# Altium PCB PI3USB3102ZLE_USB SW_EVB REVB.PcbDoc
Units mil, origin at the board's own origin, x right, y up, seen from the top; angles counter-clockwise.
Board outline 3200 x 2700 mil, 4 copper layers (Top Layer, InternalPlane1, InternalPlane2, Bottom Layer); 46 components, 36 nets, 154 pads, 58 vias.
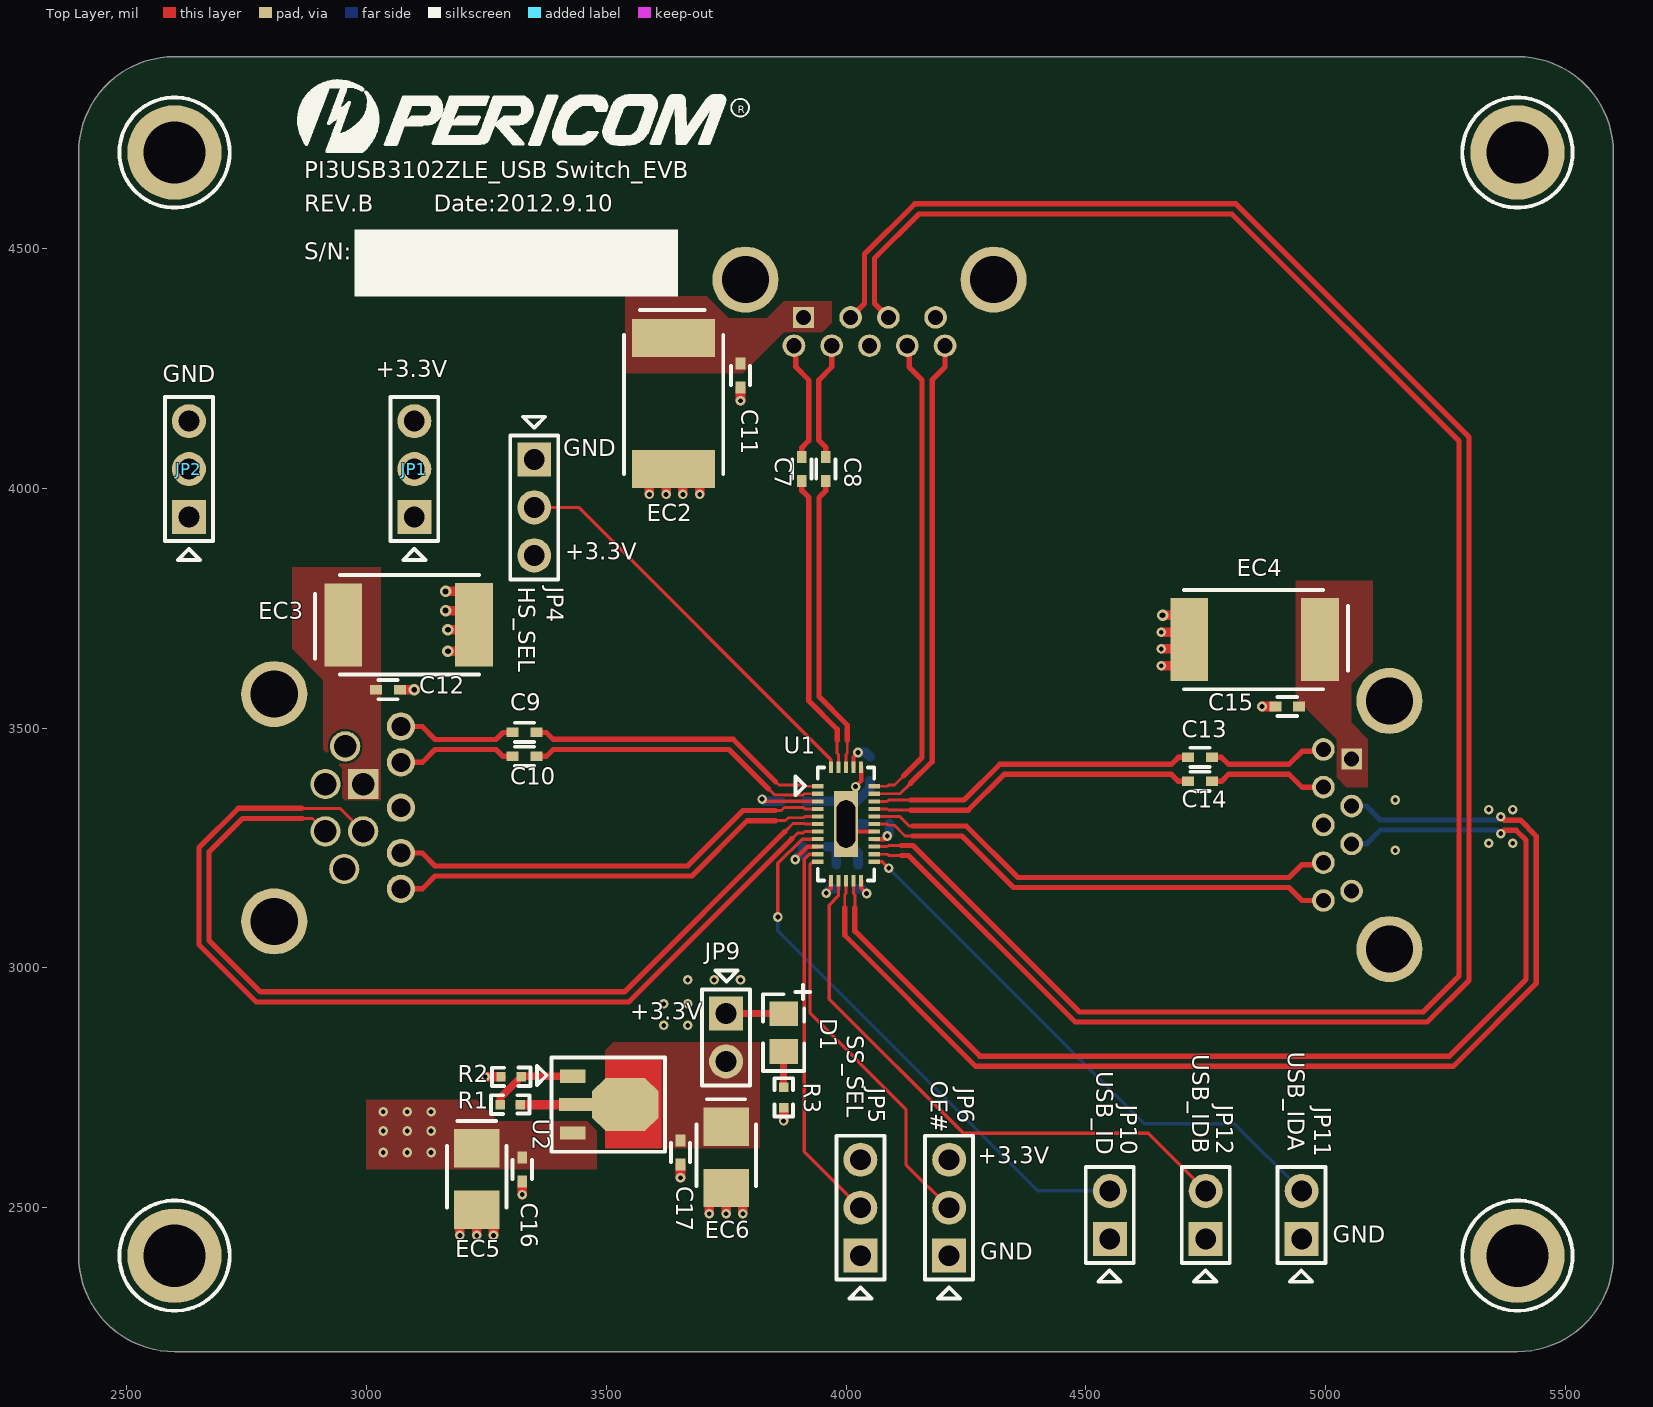
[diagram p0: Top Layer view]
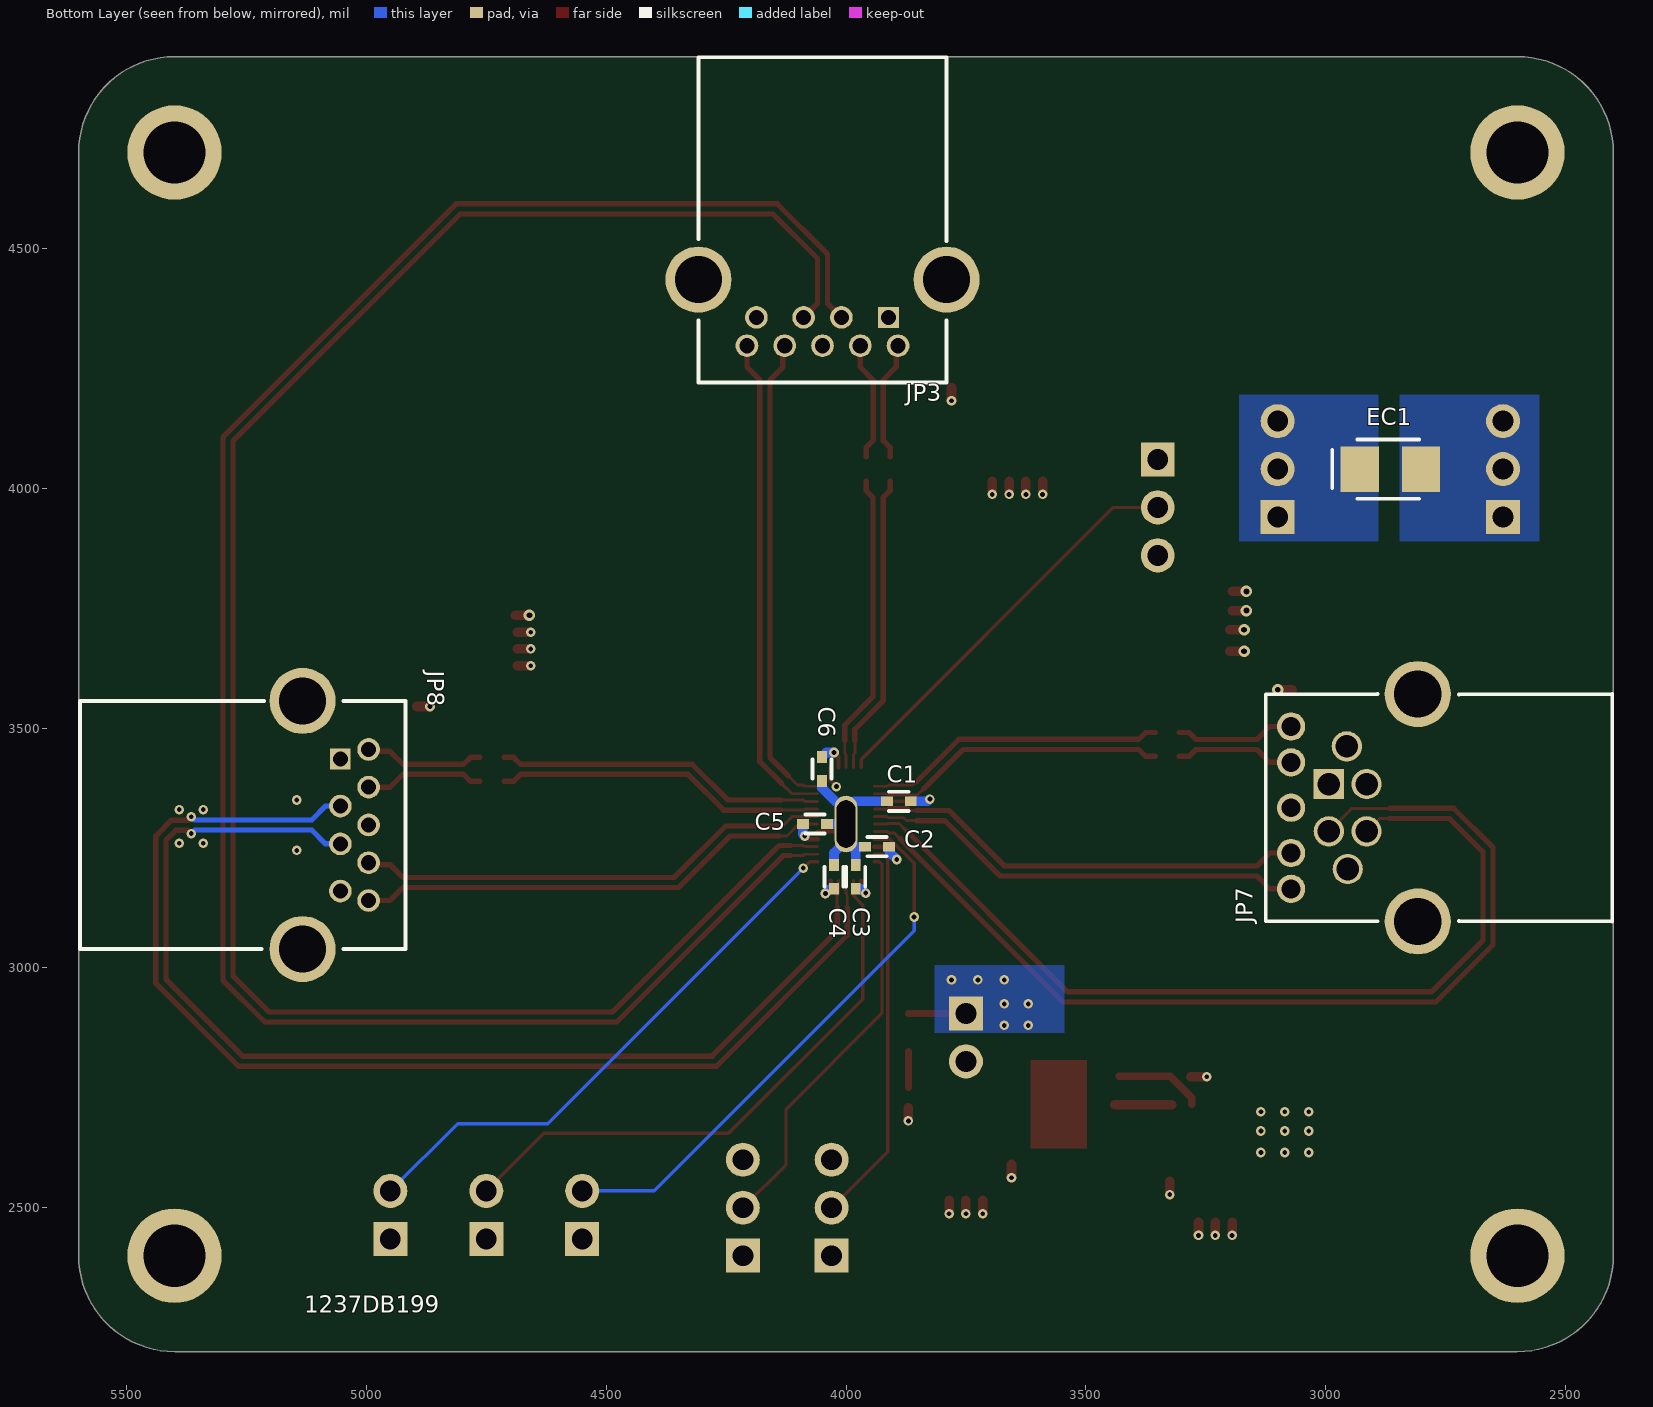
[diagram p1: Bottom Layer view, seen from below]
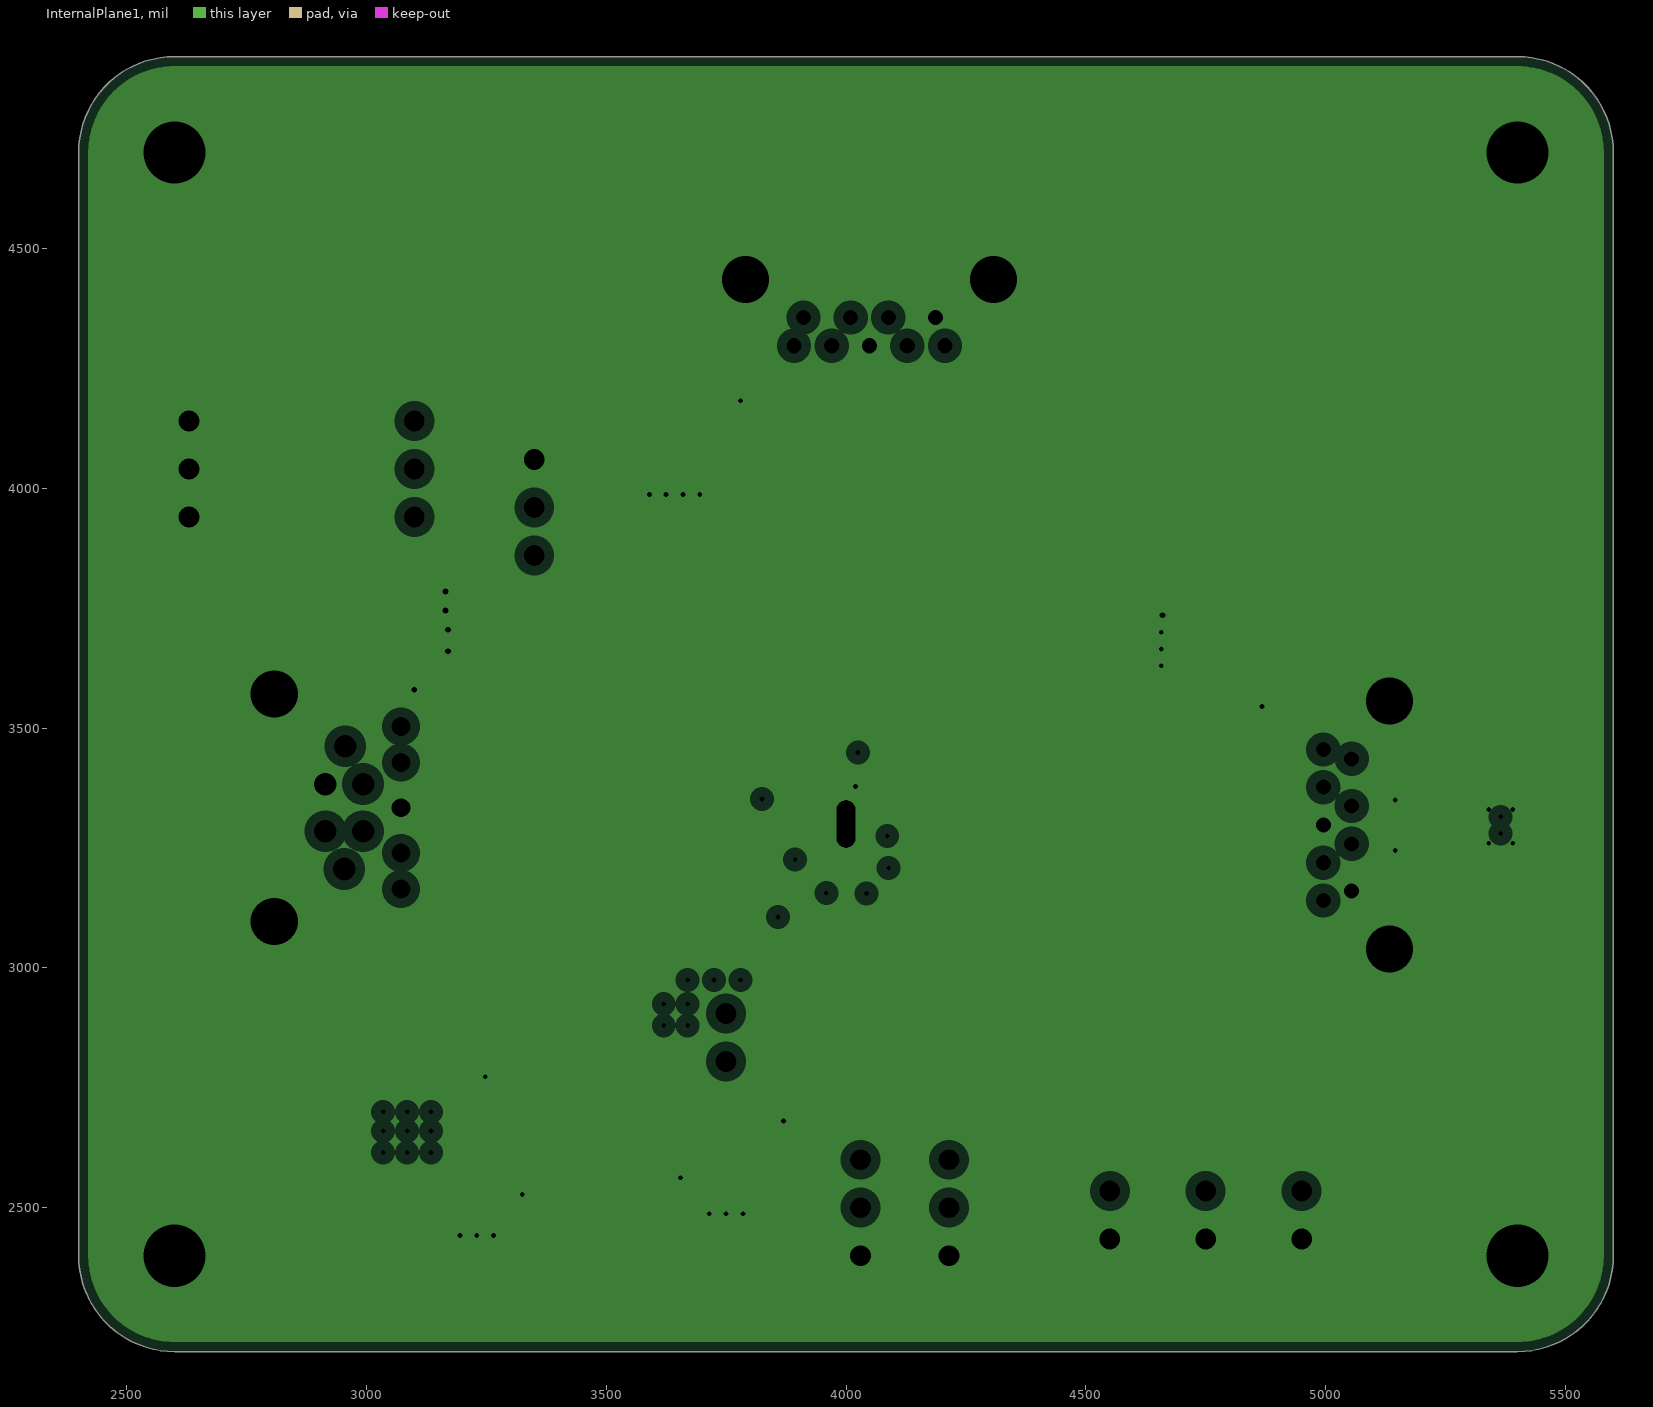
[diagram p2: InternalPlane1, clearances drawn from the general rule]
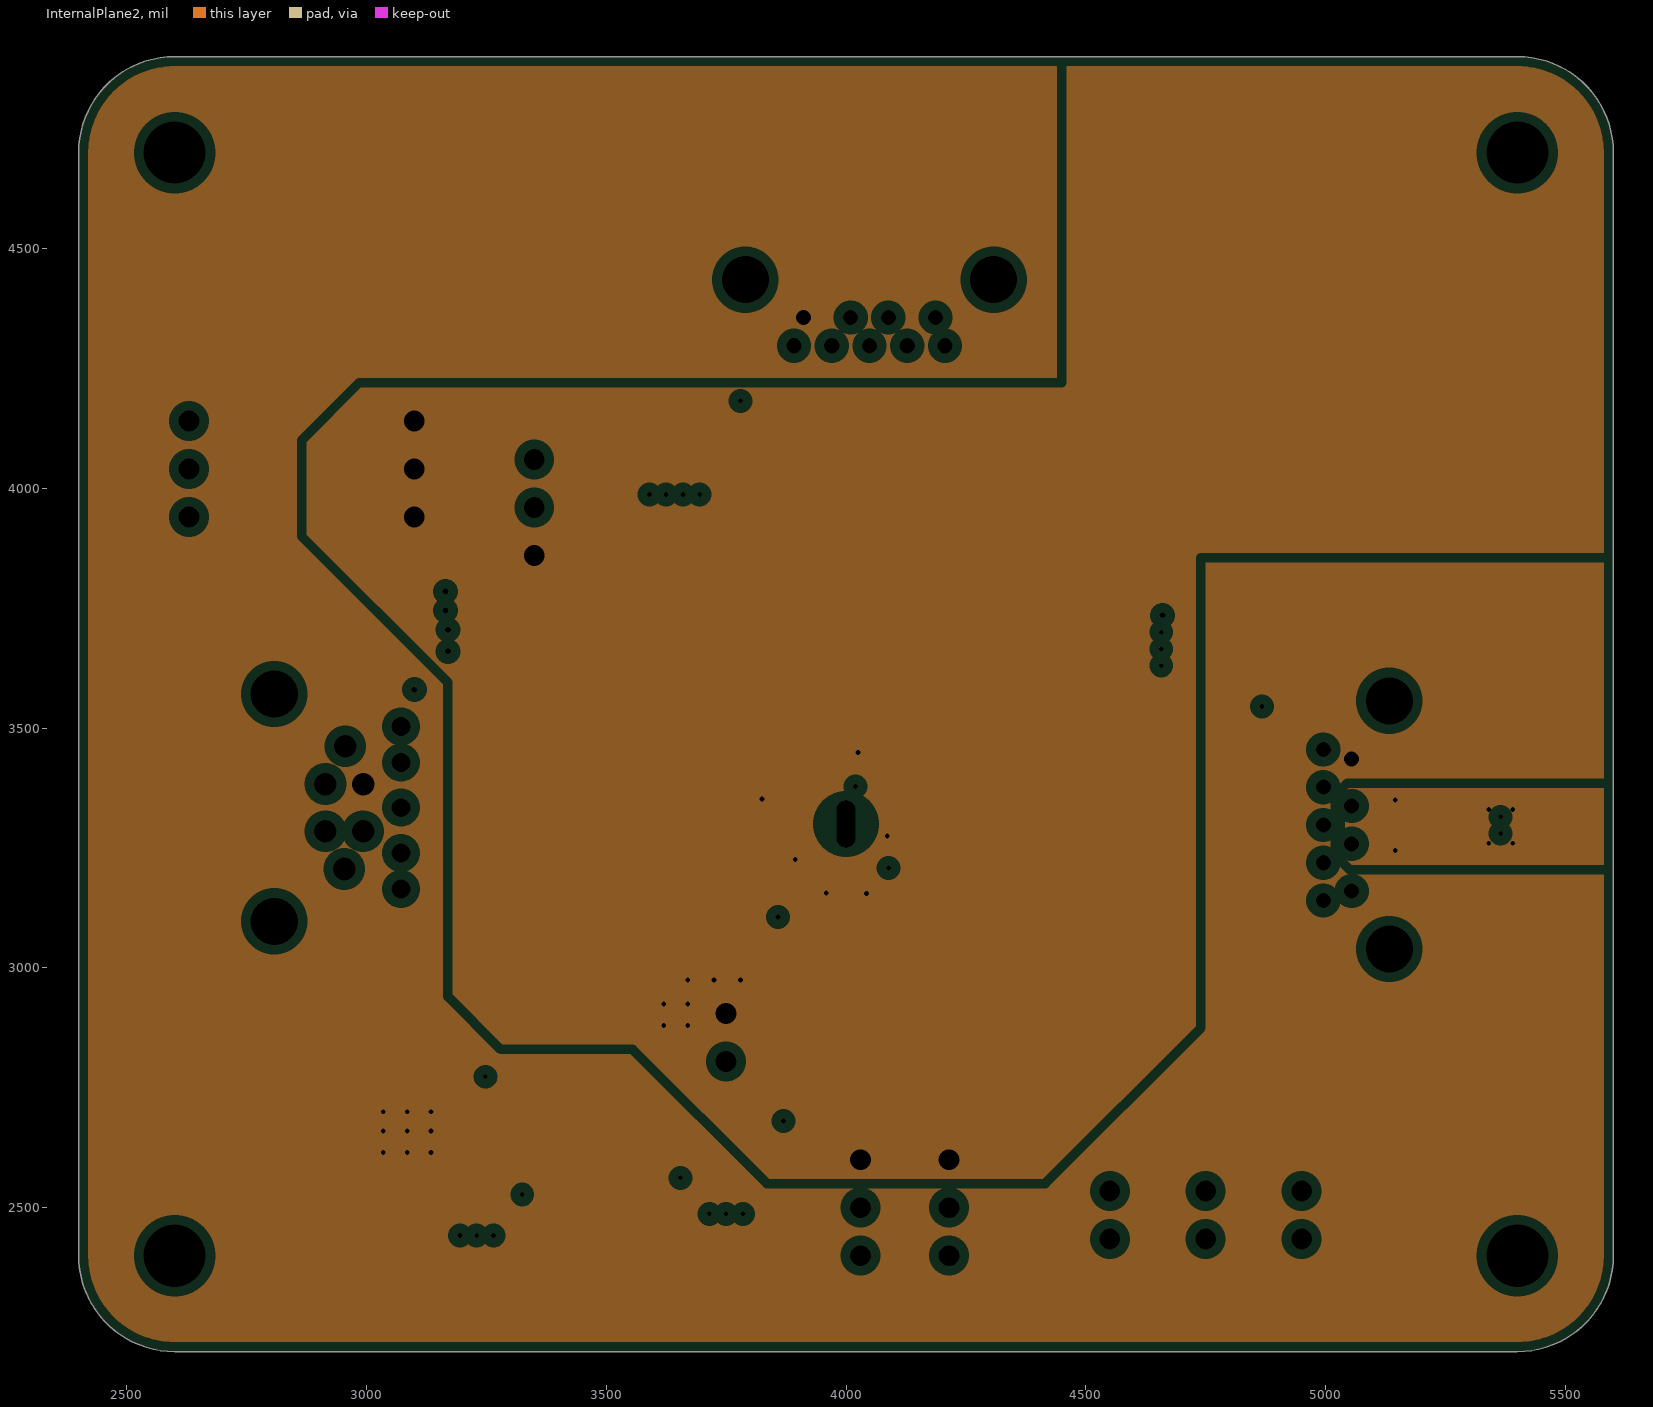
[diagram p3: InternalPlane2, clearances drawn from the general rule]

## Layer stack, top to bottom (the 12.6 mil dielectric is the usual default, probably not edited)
Top Layer: signal copper 1.4
Dielectric: core 12.6, FR-4, Dk 4.8
InternalPlane1: plane copper 1.4, net GND
Dielectric: prepreg 12.6, FR-4, Dk 4.8
InternalPlane2: plane copper 1.4, net VBUS_5V
Dielectric: core 12.6, FR-4, Dk 4.8
Bottom Layer: signal copper 1.4

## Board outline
2400,2400 ccw(c2600,2400) 2600,2200 5400,2200 ccw(c5400,2400) 5600,2400 5600,4700 ccw(c5400,4700) 5400,4900 2600,4900 ccw(c2600,4700) 2400,4700

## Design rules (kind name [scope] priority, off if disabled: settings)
Clearance [All] p1: gap=5
ComponentClearance [All] p1: gap=0 collisioncheckmode=3 verticalgap=0
DiffPairsRouting [All] p1: maxlimit=10 minlimit=10 mostfreqgap=10 maxuncoupledlength=500
HoleSize [All] p1: absolutevalues=TRUE maxlimit=500 minlimit=1 maxpercent=80.000 minpercent=20.000
PlaneClearance [All] p1: clearance=20
PlaneConnect [All] p1: planeconnectstyle=Direct reliefexpansion=20 reliefentries=4 reliefconductorwidth=10 reliefairgap=10
PolygonConnect [All] p1: connectstyle=Direct reliefconductorwidth=10 reliefentries=4 polygonreliefangle="90 Angle"
RoomDefinition "PI3USB3102ZLE USB SW EV" [InComponentClass('PI3USB3102ZLE USB SW EV')] p1: confinementstyle=ConfineIn formatcopy=TRUE lockcomponents=FALSE outline 80,235 17230,235 17230,6635 80,6635
RoutingVias [All] p1: holewidth=28 width=50 viastyle="Through Hole" minholewidth=8 minwidth=10 maxholewidth=28 maxwidth=50
SolderMaskExpansion [All] p1: expansion=4
TestPointUsage [All] p1: valid=0 allowmultiple=FALSE
Testpoint [All] p1: side=15 testpointundercomponent=TRUE minsize=40 maxsize=100 preferedsize=60 minholesize=0 maxholesize=40 preferedholesize=32 testpointgrid=1 style=1023 order=0-112345678
Width [All] p1: maxlimit=150 minlimit=5 preferedwidth=10
14 further rules are at their usual default settings.

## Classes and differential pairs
component class "PI3USB3102ZLE USB SW EV": C1 C2 C3 C4 C5 C6 C7 C8 C9 C10 C11 C12 C13 C14 C15 C16 C17 D1 EC1 EC2 EC3 EC4 EC5 EC6 JP1 JP2 JP3 JP4 JP5 JP6 JP7 JP8 JP9 JP10 JP11 JP12 R1 R2 R3 U1 U2
differential pair NewDifferentialPair12: +TX+B -TX-B
differential pair NewDifferentialPair11: +TX+A -TX-A
differential pair NewDifferentialPair10: +TX- -TX+
differential pair NewDifferentialPair9: +RX+B -RX-B
differential pair NewDifferentialPair8: +RX+A -RX-A
differential pair NewDifferentialPair7: +RX- -RX+
differential pair NewDifferentialPair6: +NetC13_2 -NetC14_2
differential pair NewDifferentialPair5: +NetC7_2 -NetC8_2
differential pair NewDifferentialPair4: +NetC10_1 -NetC9_1
differential pair NewDifferentialPair3: +D-B -D+B
differential pair NewDifferentialPair2: +D-A -D+A
differential pair NewDifferentialPair1: +D+ -D-

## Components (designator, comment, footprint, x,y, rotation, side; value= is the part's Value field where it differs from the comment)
C1 "0.1uF" CAP@CC_0402 3890,3347.24 r0 bottom
C2 "0.1uF" CAP@CC_0402 3935,3252.76 r0 bottom
C3 "0.1uF" CAP@CC_0402 3980,3190 r90 bottom
C4 "0.1uF" CAP@CC_0402 4025,3190 r90 bottom
C5 "0.1uF" CAP@CC_0402 4065,3300 r180 bottom
C6 "0.1uF" CAP@CC_0402 4050,3415 r270 bottom
C7 "0.1u" CC_0402 3908,4040 r90 top
C8 "0.1u" CC_0402 3958,4040 r90 top
C9 "0.1u" CC_0402 3330,3491 r0 top
C10 "0.1u" CC_0402 3330,3441 r0 top
C11 "0.1uF" CC_0402 3780,4235 r270 top
C12 "0.1uF" CAP@CC_0402 3045,3580 r0 top
C13 "0.1u" CC_0402 4738,3439 r0 top
C14 "0.1u" CC_0402 4738,3389 r0 top
C15 "0.1uF" CAP@CC_0402 4920,3545 r180 top
C16 "0.1uF" CC_0402 3325,2580 r270 top
C17 "0.1uF" CC_0402 3655,2615 r270 top
D1 "LED_G" LED_0805 3870,2865 r270 top
EC1 "22UF" CAP@CT_3528 2865,4040 r180 bottom
EC2 "100U" CT_7343 3640,4195 r90 top
EC3 "100UF" CAP@CT_7343 3070,3715 r180 top
EC4 "100UF" CAP@CT_7343 4870,3685 r0 top
EC5 "22uF" CT_3528 3230,2560 r270 top
EC6 "22uF" CT_3528 3750,2605 r270 top
JP1 "3x1 Pin Header" "3x1 Pin Header" 3100,3940 r90 top
JP2 "3x1 Pin Header" "3x1 Pin Header" 2630,3940 r90 top
JP3 "CON_USB3.0 TA_RECEPTACLE" "CON_USB3.0 TA_RECEPTACLE" 4049,4435 r0 bottom
JP4 "3x1 Pin Header" "3x1 Pin Header" 3350,4060 r270 top
JP5 "3x1 Pin Header" "3x1 Pin Header" 4030,2400 r90 top
JP6 "3x1 Pin Header" "3x1 Pin Header" 4215,2400 r90 top
JP7 "CON_USB3.0 TB_RECEPTACLE" "CON_USB3.0 TB_RECEPTACLE" 3072,3334 r90 bottom locked
JP8 "CON_USB3.0 TA_RECEPTACLE" "CON_USB3.0 TA_RECEPTACLE" 5133,3298 r270 bottom locked
JP9 "2x1 Pin Header" "2x1 Pin Header" 3750,2905 r270 top
JP10 "2x1 Pin Header" "2x1 Pin Header" 4550,2435 r90 top
JP11 "2x1 Pin Header" "2x1 Pin Header" 4950,2435 r90 top
JP12 "2x1 Pin Header" "2x1 Pin Header" 4750,2435 r90 top
R1 "NP" R_0402 3300,2715 r0 top
R2 "0" R_0402 3302,2773 r180 top
R3 "510" R_0402 3870,2730 r270 top
U1 "PI3USB3102ZLE@TQFN32" TQFN32_3X6 4000,3300 r0 top locked
U2 "CJ1117-ADJ" Pow_SOT_89 3485,2715 r270 top
? "Comment" HOLE5M3M3 5400,2400 r0 top
? "Comment" HOLE5M3M3 2600,2400 r0 top
? "Comment" HOLE5M3M3 2600,4700 r0 top
? "Comment" HOLE5M3M3 5400,4700 r0 top
? "Comment" PSC_LOG 2965,4805 r0 top

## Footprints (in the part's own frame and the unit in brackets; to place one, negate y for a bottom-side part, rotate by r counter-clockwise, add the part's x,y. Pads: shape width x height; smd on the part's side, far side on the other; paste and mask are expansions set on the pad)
"2x1 Pin Header" [mm] "Pin Header 2x1 Pitch 2.54mm"
  rect 1.8x1.8 hole 1.1: 1(0,0)
  round 1.8 hole 1.1: 2(2.54,0)
  silkscreen extent -2.27,-1.27 3.81,1.27
"3x1 Pin Header" [mm] "Pin Header 3x1 Pitch 2.54mm"
  rect 1.8x1.8 / inner round 1.8 / far side rect 1.8x1.8 hole 1.1: 1(0,0)
  round 1.8 hole 1.1: 2(2.54,0) 3(5.08,0)
  silkscreen extent -2.27,-1.27 6.35,1.27
CAP@CC_0402 [mil]
  rect 25x20 smd: 1(-25,0) 2(25,0)
  silkscreen extent -20,-20 20,20
CAP@CT_3528 [mil]
  rect 80x95 smd: 1(-64,0) 2(64,0)
  silkscreen extent -121,-62 60,62
CAP@CT_7343 [mm]
  rect 2x4.4 smd: 1(3,0) 2(-3.926,-0.011)
  silkscreen extent -4.19,-2.64 4.5,2.62
CC_0402 [mil]
  rect 25x20 smd: 1(-25,0) 2(25,0)
  silkscreen extent -20,-20 20,20
"CON_USB3.0 TA_RECEPTACLE" [mm]
  rect 1.1x1.1 hole 0.8: 1(-3.5,2)
  round 1.2 hole 0.8: 2(-1,2) 3(1,2) 4(3.5,2) 5(4,3.5) 6(2,3.5) 7(0,3.5) 8(-2,3.5) 9(-4,3.5)
  round 3.5 hole 2.5: 20(-6.57,0) 20(6.57,0)
  silkscreen extent -6.57,-11.78 6.57,5.45
"CON_USB3.0 TB_RECEPTACLE" [mm]
  rect 1.6x1.6 hole 1.2: 1(1.25,-2)
  round 1.6 hole 1.2: 2(-1.25,-2) 3(-1.25,-4) 4(1.25,-4) 10(3.25,-2.95) 11(-3.25,-3)
  round 1.5 hole 1: 5(-4.3,0) 6(-2.4,0) 7(0,0) 8(2.4,0) 9(4.3,0)
  round 3.5 hole 2.5: 20(-6.02,-6.71) 20(6.02,-6.71)
  silkscreen extent -6.02,-17.01 6.02,1.34
CT_3528 [mil]
  rect 80x95 smd: 1(-64,0) 2(64,0)
  silkscreen extent -121,-62 60,62
CT_7343 [mm]
  rect 2x4.4 smd: 1(3,0) 2(-3.926,-0.011)
  silkscreen extent -4.19,-2.64 4.5,2.62
HOLE5M3M3 [mm] "HOLE, Plated"
  round 5 hole 3.3: 0(0,0)
  silkscreen extent -2.92,-2.92 2.92,2.92
LED_0805 [mm] "Chip Resistor; Body 2 x 1.3 mm (LxW typ)"
  rect 1.3x1.5 smd: 1(-1,0) 2(1,0)
  silkscreen extent -2.54,-1.09 2.03,1.4
Pow_SOT_89 [mm] "SOT-89; Body 4.6 x 4.25 mm, inc. leads (LxW max)"
  rect 0.7x1.35 smd: 1(-1.5,-1.388) 3(1.5,-1.388)
  oct 2.8x3.5 smd: 2(0,1.388)
  rect 0.7x1.9 smd: 2(0,-1.163)
  Top Layer region: -2.346,0.336 -2.346,3.302 2.322,3.302 2.323,3.303 2.323,0.338 2.325,0.336
  silkscreen extent -2.5,-3.28 2.5,3.49
PSC_LOG [mil]
  silkscreen extent -107,-103 833,45
R_0402 [mm]
  rect 0.5x0.5 smd: 1(-0.532,-0.001) 2(0.54,-0.001)
  silkscreen extent -1.02,-0.49 1.02,0.49
TQFN32_3X6 [mm]
  rect 0.6x0.22 smd: 1(-1.5,2) 2(-1.5,1.6) 3(-1.5,1.2) 4(-1.5,0.8) 5(-1.5,0.4) 6(-1.5,0) 7(-1.5,-0.4) 8(-1.5,-0.8) 9(-1.5,-1.2) 10(-1.5,-1.6) 11(-1.5,-2) 17(1.5,-2) 18(1.5,-1.6) 19(1.5,-1.2) 20(1.5,-0.8) 21(1.5,-0.4) 22(1.5,0) 23(1.5,0.4) 24(1.5,0.8) 25(1.5,1.2) 26(1.5,1.6) 27(1.5,2)
  rect 0.22x0.6 smd: 12(-0.8,-3) 13(-0.4,-3) 14(0,-3) 15(0.4,-3) 16(0.8,-3) 28(0.8,3) 29(0.4,3) 30(0,3) 31(-0.4,3) 32(-0.8,3)
  rect 1.25x3.5 smd: 33(0,0)
  oval 1.2x3 hole 1 slot 2.5 at 90 deg: 33(0,0)
  silkscreen extent -2.67,-3 1.5,3

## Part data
C1 C2 C3 C4 C5 C6 C12 C15: library part "0.01UF 0402"
C7 C8 C9 C10 C13 C14: library part C_0.1u_0402_Dup1
C11: library part C_0.1u_0402_Dup2
C16 C17: library part C_0.1u_0402
D1: library part LED_0805_G
EC1: library part "22UF 3528"
EC2: library part C_tan_100u_7343
EC3 EC4: library part "100UF 7343"
EC5 EC6: library part C_tan_22u_3528
JP9: library part "2x1 Pin Header_Dup1"
R1 R2 R3: library part R_0402
U2: library part Pow_LDO_ADJ_0

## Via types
v1: diameter 20, hole 10, Top Layer to Bottom Layer, tented both sides, 52 vias
v2: diameter 24, hole 12, Top Layer to Bottom Layer, tented both sides, 6 vias

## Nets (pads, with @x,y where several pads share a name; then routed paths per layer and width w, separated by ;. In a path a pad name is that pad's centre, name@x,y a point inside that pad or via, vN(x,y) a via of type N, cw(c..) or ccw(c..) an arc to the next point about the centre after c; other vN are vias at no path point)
+3.3V: C1.1 C2.1 C3.1 C4.1 C5.1 C6.1 D1.1 EC1.1 JP1.1 JP1.2 JP1.3 JP4.3 JP5.3 JP6.3 JP9.1 U1.3 U1.9 U1.12 U1.16 U1.20 U1.29 | length 599.1
  Top Layer w7: v1(3825,3352) 3829.76,3347.24 U1.3
  Top Layer w9: v1@3893.5,3226.5 3919.76,3252.76 U1.9 ; v1(3959,3156) 3968.5,3165.5 U1.12 ; U1.29 4015.75,3439.75 v1(4025,3449) ; U1.16 4031.5,3166.5 v1(4043,3155) ; U1.20 4079.5,3268.5 v1(4086,3275)
  Top Layer w15: JP9.1 D1.1@3869.37,2905
  Bottom Layer w20: v1(3825,3352) 3829.76,3347.24 C1.1 ; v1(3894,3226) 3910,3242 C2.1 ; v1(3959,3156) 3968,3165 C3.1 ; C4.1 4033,3165 v1(4043,3155) ; v1(4025,3449) 4041,3449 C6.1 ; v1(4086,3275) 4090,3279 C5.1
  other v1: 3620,2880 3670,2880 3620,2925 3670,2925 3670,2975 3725,2975 3780,2975
D+: JP7.3 U1.6 | length 1926.5
  Top Layer w6: 2866,3311.57 2887.73,3311.57 JP7.3 ; 3872.15,3283.85 3889.3,3301 3913.13,3301 3914.13,3300 U1.6
  Top Layer w11: 2866,3311.57 2741.57,3311.57 2672,3242 2672,3057 2779,2950 3538.3,2950 3872.15,3283.85
D+A: JP3.3 U1.19 | length 4098.7
  Top Layer w6: U1.19 4085.87,3252.76 4088.49,3255.38 4114.93,3255.38
  Top Layer w11: JP3.3 4059.5,4385.13 4059.5,4479.5 4152,4572 4804.3,4572 5278,4098.3 5278,2982.7 5203.3,2908 4486.7,2908 4139.32,3255.38 4114.93,3255.38
D+B: JP8.3 U1.15 | length 2360.8
  Top Layer w6: U1.15 4015.75,3155.08 4018.37,3152.45 4018.37,3126.01
  Top Layer w11: 4018.37,3126.01 4018.37,3076.62 4279,2816 5258,2816 5418,2976 5418,3266.3 5397.3,3287 5372,3287 v1(5365,3280)
  Bottom Layer w11: JP8.3 5085,3258.63 5113.87,3287.5 5357.5,3287.5 v1(5365,3280)
D-: JP7.2 U1.7 | length 2084.9
  Top Layer w6: 2865,3332.57 2945.47,3332.57 JP7.2 ; 3887,3269 3899.63,3281.63 3911.51,3281.63 3914.13,3284.25 U1.7
  Top Layer w11: 2865,3332.57 2732.88,3332.57 2651,3250.7 2651,3048.3 2770.3,2929 3547,2929 3887,3269
D-A: JP3.2 U1.18 | length 4203.1
  Top Layer w6: U1.18 4085.87,3237.01 4088.49,3234.38 4114.93,3234.38
  Top Layer w11: JP3.2 4038.5,4385.13 4038.5,4488.2 4143.3,4593 4813,4593 5299,4107 5299,2974 5212,2887 4478,2887 4130.62,3234.38 4114.93,3234.38
D-B: JP8.2 U1.14 | length 2464.8
  Top Layer w6: 3997.37,3126.01 3997.37,3152.45 4000,3155.08 U1.14
  Top Layer w11: 3997.37,3126.01 3997.37,3067.93 4270.3,2795 5266.7,2795 5439,2967.3 5439,3275 5406,3308 5372,3308 v1(5365,3315)
  Bottom Layer w11: JP8.2 5085,3337.37 5113.87,3308.5 5358.5,3308.5 v1(5365,3315)
GND: ?.0 C1.2 C2.2 C3.2 C4.2 C5.2 C6.2 C11.2 C12.2 C15.2 C16.2 C17.2 EC1.2 EC2.2 EC3.2 EC4.2 EC5.2 EC6.2 JP2.1 JP2.2 JP2.3 JP3.4 JP3.7 JP3.20 JP4.1 JP5.1 JP6.1 JP7.4 JP7.7 JP7.20 JP8.4 JP8.7 JP8.20 JP10.1 JP11.1 JP12.1 R2.2 R3.2 U1.21 U1.28 U1.33 | length 1067.4
  Top Layer w9: v1(4020,3378) 4031.5,3389.5 U1.28 ; U1.33@4023.25,3284.25 U1.21
  Top Layer w20: C12.2 v2(3100,3580) ; v2(3165,3745) EC3.2@3195,3745 ; v2(3165,3785) EC3.2@3195,3785 ; v2(3170,3660) EC3.2@3200,3660 ; v2(3170,3705) EC3.2@3200,3705 ; v1(3195,2442.3) EC5.2@3195,2470 ; v1(3230,2442.3) EC5.2@3230,2470 ; v1(3248.03,2773.03) R2.2 ; v1(3265,2442.3) EC5.2@3265,2470 ; v1(3325,2527.3) C16.2 ; v1(3590,3987.3) EC2.2@3590,4015 ; v1(3625,3987.3) EC2.2@3625,4015 ; v1(3655,2562.3) C17.2 ; v1(3660,3987.3) EC2.2@3660,4015 ; v1(3695,3987.3) EC2.2@3695,4015 ; v1(3715,2487.3) EC6.2@3715,2515 ; v1(3750,2487.3) EC6.2@3750,2515 ; v1(3780,4182.3) C11.2 ; v1(3785,2487.3) EC6.2@3785,2515 ; v1(3869.97,2681.03) R3.2 ; v1(4657.3,3630) EC4.2@4685,3630 ; v1(4657.3,3665) EC4.2@4685,3665 ; v1(4657.3,3700) EC4.2@4685,3700 ; v2(4660,3735) EC4.2@4690,3735 ; v1(4867.3,3545) C15.2
  Bottom Layer w20: C1.2 U1.33@3982.76,3347.24 ; C2.2 U1.33@3987.76,3252.76 ; C3.2 3980,3245 U1.33@3990,3255 ; U1.33@4005,3260 4025,3240 C4.2 ; U1.33@4015,3300 C5.2 ; U1.33@4020,3345 4050,3375 C6.2
  other v1: 5145,3245 5340,3260 5390,3260 5340,3330 5390,3330 5145,3350
HS_SEL: JP4.2 U1.32 | length 852.6
  Top Layer w7: JP4.2 3443,3960 3968.5,3434.5 U1.32
NetC7_2: C7.2 JP3.9 | length 249.3
  Top Layer w11: JP3.9@3895.46,4297.2 3895.46,4252.68 3922.36,4225.78 3922.36,4099.36 3908,4085 C7.2
NetC8_2: C8.2 JP3.8 | length 249.4
  Top Layer w11: C8.2 3958,4085 3943.36,4099.64 3943.36,4225.78 3970.26,4252.68 JP3.8
NetC9_1: C9.1 JP7.9 | length 250.2
  Top Layer w11: JP7.9 3116.53,3503.29 3143.43,3476.39 3270.39,3476.39 3285,3491 C9.1
NetC10_1: C10.1 JP7.8 | length 250.1
  Top Layer w11: JP7.8 3116.53,3428.49 3143.43,3455.39 3270.61,3455.39 3285,3441 C10.1
NetC13_2: C13.2 JP8.9 | length 249.3
  Top Layer w11: C13.2 4783,3439 4797.36,3424.64 4923.78,3424.64 4950.68,3451.54 JP8.9@4995.2,3451.54
NetC14_2: C14.2 JP8.8 | length 249.4
  Top Layer w11: C14.2 4783,3389 4797.64,3403.64 4923.78,3403.64 4950.68,3376.74 JP8.8
NetC17_1: C17.1 EC6.1 JP9.2 R1.2 U2.2 | length 117.9
  Top Layer w20: R1.2 U2.2@3439.18,2714.97
NetD1_2: D1.2 R3.1 | length 74.6
  Top Layer w15: R3.1 D1.2
NetR1_1: R1.1 R2.1 U2.1 | length 184.1
  Top Layer w15: R1.1 3279.05,2729.13 3323.98,2774.06 U2.1
OE#: JP6.2 U1.11 | length 854.2
  Top Layer w7: U1.11 3930.26,3221.26 3925,3216 3925,2905 4125,2705 4125,2590 JP6.2
RX+: JP7.6 U1.4 | length 931.5
  Top Layer w6: 3853,3328 3865.3,3328 3871.42,3334.12 3911.51,3334.12 3914.13,3331.5 U1.4
  Top Layer w11: JP7.6 3116.53,3239.51 3143.43,3212.61 3669.91,3212.61 3785.3,3328 3853,3328
RX+A: JP3.6 U1.27 | length 994.1
  Top Layer w6: U1.27 4085.87,3378.74 4088.49,3381.37 4101.37,3381.37 4120,3400
  Top Layer w11: 4120,3400 4158.58,3438.58 4158.58,4225.78 4131.68,4252.68 JP3.6@4131.68,4297.2
RX+B: JP8.6 U1.23 | length 1000
  Top Layer w6: U1.23 4112.25,3315.75 4132,3296 4139,3296
  Top Layer w11: 4139,3296 4250.7,3296 4358.28,3188.42 4923.78,3188.42 4950.68,3215.32 JP8.6@4995.2,3215.32
RX-: JP7.5 U1.5 | length 931.5
  Top Layer w6: 3853,3307 3874,3307 3880.12,3313.12 3911.51,3313.12 3914.13,3315.75 U1.5
  Top Layer w11: JP7.5 3116.53,3164.71 3143.43,3191.61 3678.61,3191.61 3794,3307 3853,3307
RX-A: JP3.5 U1.26 | length 1026.7
  Top Layer w6: U1.26 4112.69,3362.99 4134.85,3385.15
  Top Layer w11: 4134.85,3385.15 4179.58,3429.88 4179.58,4225.78 4206.48,4252.68 JP3.5
RX-B: JP8.5 U1.22 | length 1002.2
  Top Layer w6: U1.22 4085.87,3300 4088.49,3297.37 4100.93,3297.37 4123.3,3275 4139,3275
  Top Layer w11: 4139,3275 4242,3275 4349.58,3167.42 4923.78,3167.42 4950.68,3140.52 JP8.5
SS_SEL: JP5.2 U1.10 | length 807.6
  Top Layer w7: U1.10 3923.01,3237.01 3913,3227 3913,2617 JP5.2
TX+: C9.2 U1.1 | length 632.4
  Top Layer w6: 3853.22,3388.22 3860.06,3381.37 3911.51,3381.37 3914.13,3378.74 U1.1
  Top Layer w11: C9.2 3375,3491 3389.5,3476.5 3764.93,3476.5 3853.22,3388.22
TX+A: C7.1 U1.31 | length 628.5
  Top Layer w6: 3981.63,3473.99 3981.63,3447.55 3984.25,3444.92 U1.31
  Top Layer w11: C7.1 3908,3995 3922.5,3980.5 3922.5,3556.8 3981.63,3497.68 3981.63,3473.99
TX+B: C13.1 U1.25 | length 692
  Top Layer w6: U1.25 4085.87,3347.24 4088.49,3349.87 4135,3349.87
  Top Layer w11: 4135,3349.87 4246.17,3349.87 4320.8,3424.5 4678.5,3424.5 4693,3439 C13.1
TX-: C10.2 U1.2 | length 632.4
  Top Layer w6: 3838.37,3373.37 3851.37,3360.37 3911.51,3360.37 3914.13,3362.99 U1.2
  Top Layer w11: C10.2 3375,3441 3389.5,3455.5 3756.23,3455.5 3838.37,3373.37
TX-A: C8.1 U1.30 | length 628.5
  Top Layer w6: U1.30 4000,3444.92 4002.63,3447.55 4002.63,3473.99
  Top Layer w11: C8.1 3958,3995 3943.5,3980.5 3943.5,3565.5 4002.63,3506.37 4002.63,3473.99
TX-B: C14.1 U1.24 | length 692
  Top Layer w6: U1.24 4085.87,3331.5 4088.49,3328.87 4135,3328.87
  Top Layer w11: 4135,3328.87 4254.87,3328.87 4329.5,3403.5 4678.5,3403.5 4693,3389 C14.1
USB_ID: JP10.2 U1.8 | length 1161.4
  Top Layer w7: v1(3858,3106) 3858,3218 3908.5,3268.5 U1.8
  Bottom Layer w7: v1(3858,3106) 3858,3077 4400,2535 JP10.2
USB_IDA: JP11.2 U1.17 | length 1175.2
  Top Layer w7: U1.17 4075.74,3221.26 v1(4089,3208)
  Bottom Layer w7: v1(4089,3208) 4622,2675 4810,2675 JP11.2
USB_IDB: JP12.2 U1.13 | length 1205.5
  Top Layer w7: U1.13 3984.25,3150.25 3965,3131 3965,2935 4245,2655 4630,2655 JP12.2
VBUS_5V: C11.1 C12.1 C15.1 C16.1 EC2.1 EC3.1 EC4.1 EC5.1 JP3.1 JP7.1 JP8.1 U2.3
  other v1: 3035,2615 3085,2615 3135,2615 3035,2660 3085,2660 3135,2660 3035,2700 3085,2700 3135,2700
pads on no net: JP7.10 JP7.11

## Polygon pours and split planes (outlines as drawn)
VBUS_5V on Top Layer "Bottom Layer-No Net" (solid, pour order 1001): 5088,3377 5043,3377 5023,3397 5023,3477 4938,3562 4938,3807 5098,3807 5098,3637 5058,3597 5053,3592 5053,3532 5053,3512 5088,3477 5088,3377
VBUS_5V on Top Layer "Bottom Layer-No Net" (solid, pour order 1000): 3970,4390 3970,4345 3950,4325 3870,4325 3785,4240 3540,4240 3540,4400 3710,4400 3750,4360 3755,4355 3815,4355 3835,4355 3870,4390 3970,4390
VBUS_5V on Top Layer "Bottom Layer-No Net" (solid, pour order 1000): 3385,2680 3460,2680 3480,2660 3480,2580 3000,2580 3000,2725 3230,2725 3270,2685 3275,2680 3385,2680
NetC17_1 on Top Layer "Bottom Layer-No Net" (solid, pour order 1001): 3498.32,2623.56 3498.32,2828.32 3515,2845 3820,2845 3820,2625 3818.56,2623.56 3498.32,2623.56
VBUS_5V on Top Layer "Bottom Layer-No Net" (solid, pour order 1000): 2950,3355 2955,3350 3030,3350 3030,3835 2845,3835 2845,3665 2910,3600 2910,3460 2910,3455 2950,3415 2950,3355
GND on Bottom Layer "Bottom Layer-No Net" (solid, pour order 1003): 2845,3890 2845,4195 2555,4195 2555,3890 2845,3890
+3.3V on Bottom Layer "Bottom Layer-No Net" (solid, pour order 1002): 2890,4195 2890,3890 3180,3890 3180,4195 2890,4195
+3.3V on Bottom Layer "Bottom Layer-No Net" (solid, pour order 1002): 3815,2865 3815,3005 3545,3005 3545,2865 3815,2865
GND on InternalPlane1 (split plane): 5423.48,4878.35 5446.56,4873.76 5468.84,4866.19 5489.94,4855.79 5509.51,4842.71 5527.2,4827.2 5542.71,4809.51 5555.78,4789.94 5566.19,4768.84 5573.76,4746.56 5578.35,4723.48 5579.82,4701.05 5579.61,4700 5579.61,2400 5579.82,2398.95 5578.35,2376.52 5573.76,2353.44 5566.19,2331.16 5555.78,2310.06 5542.71,2290.49 5527.2,2272.8 5509.51,2257.29 5489.94,2244.21 5468.84,2233.81 5446.56,2226.24 5423.48,2221.65 5401.05,2220.18 5400,2220.39 2600,2220.39 2598.95,2220.18 2576.52,2221.65 2553.44,2226.24 2531.16,2233.81 2510.06,2244.21 2490.49,2257.29 2472.8,2272.8 2457.29,2290.49 2444.22,2310.06 2433.81,2331.16 2426.24,2353.44 2421.65,2376.52 2420.18,2398.95 2420.39,2400 2420.39,4700 2420.18,4701.05 2421.65,4723.48 2426.24,4746.56 2433.81,4768.84 2444.21,4789.94 2457.29,4809.51 2472.8,4827.2 2490.49,4842.71 2510.06,4855.78 2531.16,4866.19 2553.44,4873.76 2576.52,4878.35 2598.95,4879.82 2600,4879.61 5400,4879.61 5401.05,4879.82
GND on InternalPlane2 (split plane): 5579.61,3215.2 5054.22,3215.2 5030.2,3239.22 5030.2,3265.78 5037.21,3272.79 5039.42,3276.1 5040.2,3280 5040.2,3315 5039.42,3318.9 5037.21,3322.21 5030.2,3329.22 5030.2,3355.78 5049.22,3374.8 5579.61,3374.8
+3.3V on InternalPlane2 (split plane): 5423.48,4878.35 5446.56,4873.76 5468.84,4866.19 5489.94,4855.79 5509.51,4842.71 5527.2,4827.2 5542.71,4809.51 5555.78,4789.94 5566.19,4768.84 5573.76,4746.56 5578.35,4723.48 5579.82,4701.05 5579.61,4700 5579.61,3865.2 4740,3865.2 4736.1,3864.42 4732.79,3862.21 4730.58,3858.9 4729.8,3855 4729.8,2879.22 4410.78,2560.2 3839.22,2560.2 3562.21,2837.21 3558.9,2839.42 3555,2840.2 3284.22,2840.2 3180.2,2944.22 3180.2,3595 3179.42,3598.9 3177.21,3602.21 2875.2,3904.22 2875.2,4095.78 2989.22,4209.8 4450,4209.8 4453.9,4210.58 4457.21,4212.79 4459.42,4216.1 4460.2,4220 4460.2,4879.61 5400,4879.61 5401.05,4879.82
VBUS_5V on InternalPlane2 (split plane): 2600,4879.61 4439.8,4879.61 4439.8,4230.2 2985,4230.2 2981.1,4229.42 2977.79,4227.21 2857.79,4107.21 2855.58,4103.9 2854.8,4100 2854.8,3900 2855.58,3896.1 2857.79,3892.79 3159.8,3590.78 3159.8,2940 3160.58,2936.1 3162.79,2932.79 3272.79,2822.79 3276.1,2820.58 3280,2819.8 3550.78,2819.8 3827.79,2542.79 3831.1,2540.58 3835,2539.8 4415,2539.8 4418.9,2540.58 4422.21,2542.79 4747.21,2867.79 4749.42,2871.1 4750.2,2875 4750.2,3844.8 5579.61,3844.8 5579.61,3395.2 5045,3395.2 5041.1,3394.42 5037.79,3392.21 5012.79,3367.21 5010.58,3363.9 5009.8,3360 5009.8,3325 5010.58,3321.1 5012.79,3317.79 5019.8,3310.78 5019.8,3284.22 5012.79,3277.21 5010.58,3273.9 5009.8,3270 5009.8,3235 5010.58,3231.1 5012.79,3227.79 5042.79,3197.79 5046.1,3195.58 5050,3194.8 5579.61,3194.8 5579.61,2400 5579.82,2398.95 5578.35,2376.52 5573.76,2353.44 5566.19,2331.16 5555.78,2310.06 5542.71,2290.49 5527.2,2272.8 5509.51,2257.29 5489.94,2244.21 5468.84,2233.81 5446.56,2226.24 5423.48,2221.65 5401.05,2220.18 5400,2220.39 2600,2220.39 2598.95,2220.18 2576.52,2221.65 2553.44,2226.24 2531.16,2233.81 2510.06,2244.21 2490.49,2257.29 2472.8,2272.8 2457.29,2290.49 2444.22,2310.06 2433.81,2331.16 2426.24,2353.44 2421.65,2376.52 2420.18,2398.95 2420.39,2400 2420.39,4700 2420.18,4701.05 2421.65,4723.48 2426.24,4746.56 2433.81,4768.84 2444.21,4789.94 2457.29,4809.51 2472.8,4827.2 2490.49,4842.71 2510.06,4855.78 2531.16,4866.19 2553.44,4873.76 2576.52,4878.35 2598.95,4879.82

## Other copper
InternalPlane2 (plane layer: these items are gaps in the copper):
  lines w20: 4450,4900 4450,4220 2985,4220 2865,4100 2865,3900 3170,3595 3170,2940 3280,2830 3555,2830 3835,2550 4415,2550 4740,2875 4740,3855 5600,3855 ; 5600,3205 5050,3205 5020,3235 5020,3270 5030,3280 5030,3315 5020,3325 5020,3360 5045,3385 5600,3385

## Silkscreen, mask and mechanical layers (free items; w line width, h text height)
Top Overlay:
  rectangle: 2975,4400 3650,4540
  text "PI3USB3102ZLE_USB Switch_EVB" at 2870,4635 h60
  text "REV.B" at 2870,4565 h60
  text "Date:2012.9.10" at 3140,4565 h60
  text "S/N:" at 2870,4465 h60
  text "+3.3V" at 3020,4220 h60
  text "GND" at 2575,4210 h60
  text "GND" at 3410,4055 h60
  text "+3.3V" at 3415,3840 h60
  text "HS_SEL" at 3305,3795 h60 r270
  text "+3.3V" at 3550,2880 h60
  text "SS_SEL" at 3990,2860 h60 r270
  text "USB_IDA" at 4910,2825 h60 r270
  text "USB_IDB" at 4710,2820 h60 r270
  text "USB_ID" at 4510,2785 h60 r270
  text "OE#" at 4165,2765 h60 r270
  text "+3.3V" at 4275,2580 h60
  text "GND" at 5015,2415 h60
  text "GND" at 4280,2380 h60
Bottom Overlay:
  text "1237DB199" at 5130,2270 h60
Mechanical 1:
  the board outline again, w8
